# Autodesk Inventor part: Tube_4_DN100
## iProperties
Shininess: 64.0
Length Units: 11269
Angle Units: 11279
Time Units: 11290
Mass Units: 11283
Length Display Precision: 3
Angle Display Precision: 2
Compacted: True
Part Number: Tube_4_DN100
Document SubType Name: Modeling
Created: 2008-04
Material: Par défaut
Designer: plup
Density: 0.0
Volumn: 0.0
Area: 0.0
PropertySet Name: Model Information
Control State: 0
Master: False
Checked Out: False
MATIERE_PIECE: X2CrNi 18-11
OBSERVATIONS: Lg.: .......
DESIGNATION: Tube 4
Author: plup
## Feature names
1. Extrusion1
